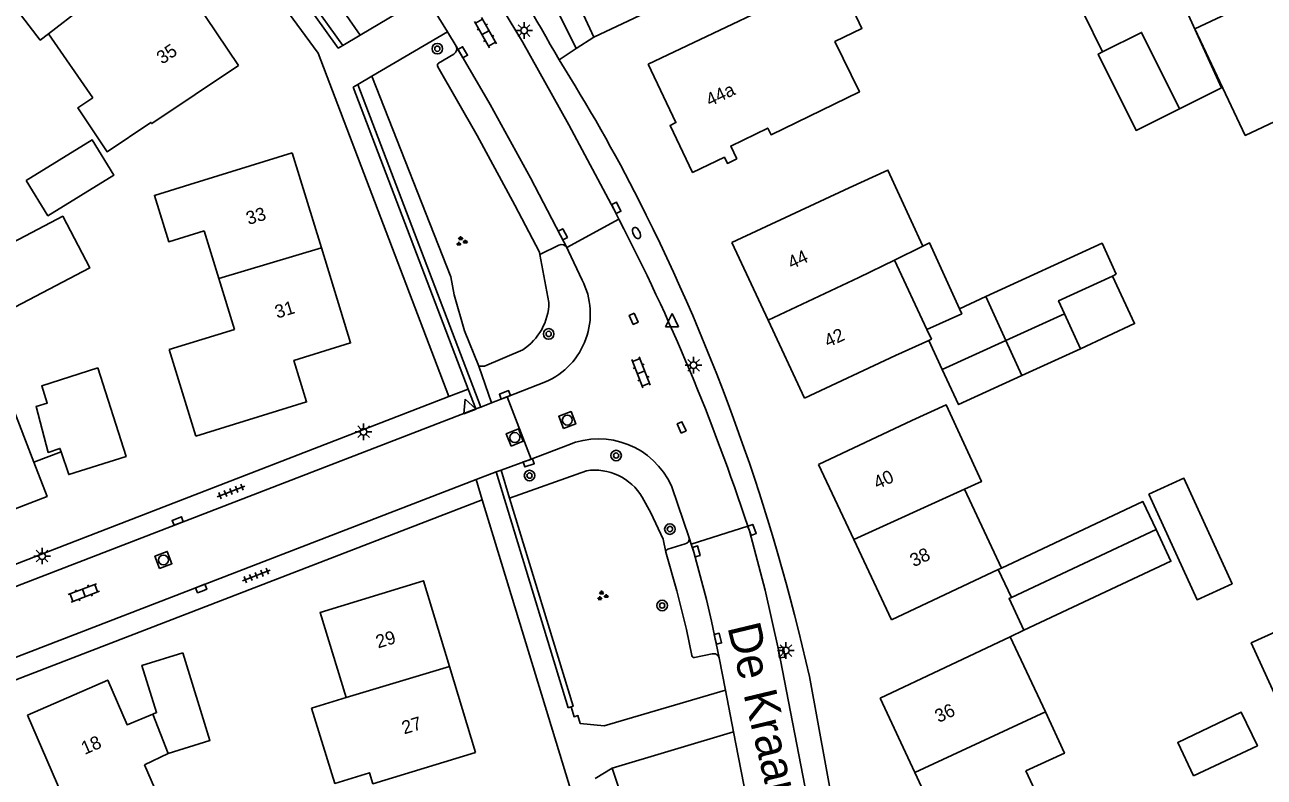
# Model space of a CAD drawing. Extents: x 136000 to 138005, y 398500 to 400500.
# Drawn here: x 137437.9 to 137531.8, y 399206.8 to 399263.7 of the extents above; entities that cross this region are included whole.
import ezdxf

# ---------------------------------------------------------------- set-up
doc = ezdxf.new("R2010")
doc.units = 0
for name, color, linetype in [('gg-afsc-erfafscheiding', 7, 'Continuous'), ('gg-anno-huisnummerreeks BGT', 7, 'Continuous'), ('gg-anno-openbare ruimte label', 7, 'Continuous'), ('gg-bbg-bijgebouw', 7, 'Continuous'), ('gg-bbg-gedigitaliseerde bebouwing', 7, 'Continuous'), ('gg-bbg-gedigitaliseerde bijgebouw', 7, 'Continuous'), ('gg-bbg-hoofdgebouw', 7, 'Continuous'), ('gg-bbg-luifel en loopbrug', 7, 'Continuous'), ('gg-bbg-tussenscheiding', 7, 'Continuous'), ('gg-knt-verharding', 7, 'Continuous'), ('gg-knt-verharding nz', 7, 'Continuous'), ('gt-grn-groengrens', 7, 'Continuous'), ('gt-grn-vlakafsluiter', 7, 'Continuous'), ('gt-grn-weggrens', 7, 'Continuous'), ('gt-symb-boom', 7, 'Continuous'), ('gt-symb-brandkraan', 7, 'Continuous'), ('gt-symb-groenvak', 7, 'Continuous'), ('gt-symb-klinker verharding', 7, 'Continuous'), ('gt-symb-kolk', 7, 'Continuous'), ('gt-symb-kolk center center', 7, 'Continuous'), ('gt-symb-lichtmast', 7, 'Continuous'), ('gt-symb-rioolschacht', 7, 'Continuous'), ('gt-symb-tegel verharding', 7, 'Continuous'), ('gt-symb-waterafsluiter', 7, 'Continuous')]:
    doc.layers.add(name, color=color, linetype=linetype)

# ---------------------------------------------------------------- blocks, each defined once
blk = doc.blocks.new('gt0-KOLK')
at = {"layer": 'gt-symb-kolk'}
blk.add_lwpolyline([(0, 0), (0.375, 0), (0.375, 0.4), (-0.375, 0.4), (-0.375, 0), (0, 0)], dxfattribs=at)
blk = doc.blocks.new('gt0-BOOM')
at = {"layer": 'gt-symb-boom'}
for radius in [0.4, 0.2]:
    blk.add_circle((0, 0), radius, dxfattribs=at)
blk = doc.blocks.new('gt0-KL1')
at = {"layer": 'gt-symb-klinker verharding'}
for p, q in [((-1.15, 0.3), (1.15, 0.3)), ((-1, -0.3), (-1, 0.3)), ((-0.5, 0.3), (-0.5, 0.45)), ((0, -0.3), (0, 0.3)), ((0.5, 0.3), (0.5, 0.45)), ((1, -0.3), (1, 0.3)), ((-1.15, -0.3), (1.15, -0.3)), ((-0.5, -0.45), (-0.5, -0.3)), ((0.5, -0.45), (0.5, -0.3))]:
    blk.add_line(p, q, dxfattribs=at)
blk = doc.blocks.new('gt0-LMAST')
at = {"layer": 'gt-symb-lichtmast'}
for p, q in [((-0.182, 0.173), (-0.447, 0.438)), ((-0.005, 0.246), (-0.005, 0.621)), ((0.172, 0.173), (0.437, 0.438)), ((-0.255, -0.004), (-0.63, -0.004)), ((-0.182, -0.181), (-0.447, -0.446)), ((-0.005, -0.254), (-0.005, -0.629)), ((0.437, -0.446), (0.172, -0.181)), ((0.245, -0.004), (0.62, -0.004))]:
    blk.add_line(p, q, dxfattribs=at)
blk.add_circle((-0.005, -0.004), 0.25, dxfattribs=at)
blk = doc.blocks.new('gt0-BR')
at = {"layer": 'gt-symb-brandkraan'}
for centre, radius, start, end in [((-0.244, 0), 0.206, 107.56694, 252.43307), ((0.599, -2.664), 3, 106.89205, 107.56694), ((0, -0.691), 0.938, 73.10799, 106.89205), ((-0.599, -2.664), 3, 72.43309, 73.10799), ((0.244, 0), 0.206, 287.56695, 72.43309), ((0.599, 2.664), 3, 252.43307, 253.10797), ((0, 0.691), 0.938, 253.10797, 286.89206), ((-0.599, 2.664), 3, 286.89206, 287.56695)]:
    blk.add_arc(centre, radius, start, end, dxfattribs=at)
blk = doc.blocks.new('gt0-GRVAK')
at = {"layer": 'gt-symb-groenvak'}
for p, q in [((-0.11, 0.189), (-0.228, 0.24)), ((-0.182, 0.153), (0.088, 0.153)), ((-0.091, 0.211), (-0.156, 0.322)), ((-0.047, 0.214), (-0.047, 0.393)), ((-0.004, 0.211), (0.061, 0.322)), ((0.015, 0.189), (0.133, 0.24)), ((0.262, -0.052), (0.197, 0.059)), ((0.305, -0.049), (0.305, 0.13)), ((0.349, -0.052), (0.414, 0.059)), ((-0.245, -0.228), (-0.363, -0.177)), ((-0.318, -0.264), (-0.047, -0.264)), ((-0.226, -0.206), (-0.291, -0.095)), ((-0.183, -0.203), (-0.183, -0.024)), ((-0.139, -0.206), (-0.074, -0.095)), ((-0.12, -0.228), (-0.002, -0.177)), ((0.243, -0.074), (0.125, -0.023)), ((0.17, -0.11), (0.441, -0.11)), ((0.368, -0.074), (0.486, -0.023))]:
    blk.add_line(p, q, dxfattribs=at)
blk = doc.blocks.new('gt0-KOLKCC')
at = {"layer": 'gt-symb-kolk center center'}
blk.add_lwpolyline([(-0.375, 0.2), (0.375, 0.2), (0.375, -0.2), (-0.375, -0.2)], close=True, dxfattribs=at)
blk = doc.blocks.new('gt0-RS')
at = {"layer": 'gt-symb-rioolschacht'}
blk.add_lwpolyline([(-0.5, -0.5), (0.5, -0.5), (0.5, 0.5), (-0.5, 0.5)], close=True, dxfattribs=at)
blk.add_circle((0, 0), 0.375, dxfattribs=at)
blk = doc.blocks.new('gt0-WAFSL')
at = {"layer": 'gt-symb-waterafsluiter'}
for p, q in [((-0.5, -0.333), (0, 0.667)), ((0, 0.667), (0.5, -0.333)), ((0.5, -0.333), (-0.5, -0.333))]:
    blk.add_line(p, q, dxfattribs=at)
blk = doc.blocks.new('gt0-TEG1')
at = {"layer": 'gt-symb-tegel verharding'}
for p, q in [((-1.125, 0), (1.125, 0)), ((-0.9, -0.25), (-0.9, 0.25)), ((-0.45, -0.25), (-0.45, 0.25)), ((0, -0.25), (0, 0.25)), ((0.45, -0.25), (0.45, 0.25)), ((0.9, -0.25), (0.9, 0.25))]:
    blk.add_line(p, q, dxfattribs=at)

msp = doc.modelspace()

# ---------------------------------------------------------------- linework, layer by layer
at = {"layer": 'gg-afsc-erfafscheiding'}
for p, q in [((137440.667, 399231.416), (137438.592, 399230.623)), ((137513.611, 399217.909), (137512.573, 399217.419))]:
    msp.add_line(p, q, dxfattribs=at)
at = {"layer": 'gg-bbg-bijgebouw'}
for p, q in [((137481.033, 399262.812), (137478.609, 399268.051)), ((137512.664, 399220.385), (137511.664, 399222.506))]:
    msp.add_line(p, q, dxfattribs=at)
for points in [[(137489.14, 399266.43), (137487.24, 399265.52), (137487.14, 399265.71), (137481.033, 399262.812)], [(137443.464, 399237.779), (137445.593, 399231.072), (137441.252, 399229.697), (137440.667, 399231.416)], [(137513.611, 399217.909), (137512.484, 399220.3), (137512.664, 399220.385)], [(137447.607, 399211.549), (137447.9, 399211.67), (137446.79, 399215.251), (137449.89, 399216.2)], [(137526.46, 399206.883), (137525.262, 399209.418), (137530.073, 399211.704), (137531.297, 399209.161), (137526.46, 399206.883)]]:
    msp.add_lwpolyline(points, dxfattribs=at)
at = {"layer": 'gg-bbg-gedigitaliseerde bebouwing'}
for p, q in [((137439.706, 399263.064), (137443.067, 399258.213)), ((137450.43, 399251.657), (137458.18, 399254.04)), ((137491.49, 399247.27), (137500.359, 399251.401)), ((137452.615, 399244.547), (137451.51, 399248.143)), ((137503.804, 399245.927), (137505.939, 399246.975)), ((137503.804, 399245.927), (137506.259, 399240.662)), ((137453.808, 399240.667), (137452.615, 399244.547)), ((137448.86, 399239.169), (137453.808, 399240.667)), ((137503.866, 399238.698), (137506.393, 399239.853)), ((137503.866, 399238.698), (137496.99, 399235.48)), ((137498.05, 399230.46), (137505.125, 399233.778)), ((137509.106, 399228.578), (137511.901, 399222.617)), ((137515.243, 399211.726), (137512.573, 399217.419)), ((137448.785, 399208.565), (137446.993, 399207.711))]:
    msp.add_line(p, q, dxfattribs=at)
for points in [[(137485.13, 399260.76), (137499.416, 399267.555), (137501.331, 399263.463), (137499.29, 399262.47), (137501.139, 399258.666), (137494.447, 399255.413), (137494.198, 399255.926), (137491.392, 399254.562), (137491.86, 399253.6)], [(137443.067, 399258.213), (137441.929, 399257.452), (137444.146, 399254.134), (137447.472, 399256.356), (137447.533, 399256.265), (137454.11, 399260.66)], [(137505.939, 399246.975), (137503.301, 399252.746), (137500.359, 399251.401)], [(137451.51, 399248.143), (137448.825, 399247.317), (137447.744, 399250.831), (137450.43, 399251.657)], [(137506.259, 399240.662), (137506.594, 399239.945), (137506.393, 399239.853)], [(137438.592, 399230.623), (137436.883, 399235.097), (137430.181, 399232.495)], [(137509.106, 399228.578), (137510.381, 399229.161), (137507.726, 399234.967), (137505.125, 399233.778)], [(137533.687, 399218.253), (137530.833, 399216.949), (137534.06, 399209.89)], [(137459.65, 399212.01), (137461.416, 399206.307), (137464.033, 399207.118), (137464.288, 399206.292), (137472.06, 399208.65)], [(137515.243, 399211.726), (137516.675, 399208.593), (137513.754, 399207.258)], [(137446.993, 399207.711), (137448.676, 399203.841), (137445.46, 399202.444), (137444.336, 399205.033), (137441.467, 399203.787), (137438.12, 399211.49)], [(137513.754, 399207.258), (137515.158, 399204.246), (137508.2, 399200.99)]]:
    msp.add_lwpolyline(points, dxfattribs=at)
at = {"layer": 'gg-bbg-gedigitaliseerde bijgebouw'}
for p, q in [((137525.397, 399257.383), (137528.583, 399258.972)), ((137520.317, 399244.72), (137520.607, 399244.853)), ((137510.712, 399243.173), (137512.231, 399239.849)), ((137512.231, 399239.849), (137513.449, 399237.184)), ((137513.449, 399237.184), (137517.901, 399239.219))]:
    msp.add_line(p, q, dxfattribs=at)
for points in [[(137439.706, 399263.064), (137439.088, 399262.587), (137434.814, 399268.131), (137437.982, 399270.573), (137439.826, 399268.182)], [(137528.583, 399258.972), (137524.551, 399267.823), (137518.118, 399264.62), (137519.571, 399261.697)], [(137526.555, 399263.445), (137534.638, 399267.258), (137538.451, 399259.175), (137530.368, 399255.362), (137526.555, 399263.445)], [(137519.571, 399261.697), (137522.523, 399263.164), (137525.397, 399257.383)], [(137438.026, 399251.963), (137439.669, 399249.289), (137444.666, 399252.359), (137443.022, 399255.033), (137438.026, 399251.963)], [(137434.107, 399245.759), (137436.157, 399241.838), (137442.84, 399245.332), (137440.791, 399249.253), (137434.107, 399245.759)], [(137520.607, 399244.853), (137519.532, 399247.204), (137510.712, 399243.173)], [(137520.317, 399244.72), (137521.993, 399241.128), (137517.901, 399239.219)], [(137440.667, 399231.416), (137440.581, 399231.669), (137439.697, 399231.368), (137438.772, 399234.837), (137439.614, 399235.098), (137439.207, 399236.409), (137443.464, 399237.779)], [(137523.078, 399228.207), (137525.721, 399229.415), (137529.372, 399221.429), (137526.722, 399220.218), (137523.078, 399228.207)], [(137511.901, 399222.617), (137522.624, 399227.646), (137523.619, 399225.523)], [(137523.619, 399225.523), (137524.742, 399223.129), (137513.611, 399217.909)], [(137449.89, 399216.2), (137451.94, 399209.549), (137448.785, 399208.565)]]:
    msp.add_lwpolyline(points, dxfattribs=at)
at = {"layer": 'gg-bbg-hoofdgebouw'}
for p, q in [((137458.18, 399254.04), (137460.39, 399246.85)), ((137494.24, 399241.375), (137491.49, 399247.27)), ((137496.99, 399235.48), (137494.24, 399241.375)), ((137450.88, 399232.59), (137448.86, 399239.169)), ((137498.05, 399230.46), (137500.71, 399224.789)), ((137500.71, 399224.789), (137503.57, 399218.69)), ((137503.57, 399218.69), (137511.664, 399222.506)), ((137512.573, 399217.419), (137502.71, 399212.77)), ((137472.06, 399208.65), (137470.09, 399215.155)), ((137462.27, 399212.81), (137459.65, 399212.01)), ((137505.332, 399207.144), (137502.71, 399212.77)), ((137508.2, 399200.99), (137505.332, 399207.144))]:
    msp.add_line(p, q, dxfattribs=at)
for points in [[(137446.25, 399268.46), (137448.12, 399265.66), (137449.95, 399266.88), (137454.11, 399260.66)], [(137491.86, 399253.6), (137491.14, 399253.25), (137490.92, 399253.71), (137488.5, 399252.56), (137486.8, 399256.13), (137487.24, 399256.34), (137485.13, 399260.76)], [(137460.39, 399246.85), (137462.6, 399239.66), (137458.3, 399238.33), (137459.27, 399235.19), (137450.88, 399232.59)], [(137428.588, 399227.104), (137431.315, 399228.187), (137432.435, 399225.275), (137439.613, 399228.037), (137438.592, 399230.623)], [(137470.09, 399215.155), (137468.12, 399221.66), (137460.29, 399219.241), (137462.27, 399212.81)], [(137438.12, 399211.49), (137444.2, 399214.13), (137445.67, 399210.751), (137447.607, 399211.549)]]:
    msp.add_lwpolyline(points, dxfattribs=at)
at = {"layer": 'gg-bbg-luifel en loopbrug'}
for p, q in [((137510.712, 399243.173), (137508.729, 399242.248)), ((137507.42, 399237.65), (137506.393, 399239.853)), ((137512.231, 399239.849), (137507.42, 399237.65))]:
    msp.add_line(p, q, dxfattribs=at)
for points in [[(137525.397, 399257.383), (137522.108, 399255.748), (137519.234, 399261.529), (137519.571, 399261.697)], [(137508.729, 399242.248), (137506.454, 399247.223), (137505.939, 399246.975)], [(137506.259, 399240.662), (137508.901, 399241.87), (137508.729, 399242.248)], [(137513.449, 399237.184), (137508.66, 399234.995), (137507.42, 399237.65)]]:
    msp.add_lwpolyline(points, dxfattribs=at)
at = {"layer": 'gg-bbg-tussenscheiding'}
for p, q in [((137439.706, 399263.064), (137442.256, 399265.029)), ((137452.615, 399244.547), (137460.39, 399246.85)), ((137501.111, 399244.605), (137503.804, 399245.927)), ((137494.24, 399241.375), (137501.111, 399244.605)), ((137512.231, 399239.849), (137516.691, 399241.865)), ((137517.901, 399239.219), (137516.691, 399241.865)), ((137500.71, 399224.789), (137509.106, 399228.578)), ((137512.664, 399220.385), (137523.619, 399225.523)), ((137511.664, 399222.506), (137511.901, 399222.617)), ((137462.27, 399212.81), (137470.09, 399215.155)), ((137505.332, 399207.144), (137515.243, 399211.726)), ((137447.607, 399211.549), (137448.785, 399208.565))]:
    msp.add_line(p, q, dxfattribs=at)
msp.add_lwpolyline([(137516.691, 399241.865), (137516.238, 399242.857), (137520.317, 399244.72)], dxfattribs=at)
at = {"layer": 'gg-knt-verharding'}
for p, q in [((137462.006, 399262.18), (137455.776, 399270.874)), ((137468.268, 399265.902), (137463.332, 399262.968)), ((137468.268, 399265.902), (137469.945, 399263.214)), ((137463.332, 399262.968), (137462.006, 399262.18)), ((137464.208, 399259.854), (137469.945, 399263.214)), ((137469.945, 399263.214), (137470.596, 399262.112)), ((137469.268, 399260.834), (137470.416, 399261.53)), ((137463.137, 399259.227), (137464.208, 399259.854)), ((137462.787, 399259.022), (137463.137, 399259.227)), ((137471.51, 399236.158), (137462.787, 399259.022)), ((137482.93, 399249.016), (137478.981, 399246.889)), ((137482.93, 399249.016), (137482.946, 399248.983)), ((137478.384, 399247.058), (137476.947, 399246.34)), ((137478.981, 399246.889), (137479.095, 399246.593)), ((137479.095, 399246.593), (137480.146, 399244.416)), ((137472.08, 399234.663), (137471.51, 399236.158)), ((137477.374, 399236.719), (137474.459, 399235.58)), ((137432.96, 399221.251), (137470.04, 399235.59)), ((137472.454, 399234.807), (137473.28, 399235.126)), ((137474.459, 399235.58), (137473.28, 399235.126)), ((137474.459, 399235.58), (137476.281, 399230.854)), ((137434.86, 399220.31), (137472.08, 399234.663)), ((137472.08, 399234.663), (137472.454, 399234.807)), ((137476.281, 399230.854), (137479.062, 399231.927)), ((137474.002, 399230.029), (137476.281, 399230.854)), ((137472.107, 399229.308), (137473.625, 399229.893)), ((137473.625, 399229.893), (137474.002, 399230.029)), ((137479.069, 399212.034), (137473.625, 399229.893)), ((137434.276, 399214.719), (137472.107, 399229.308)), ((137486.898, 399228.829), (137486.926, 399228.764)), ((137486.926, 399228.764), (137488.252, 399224.902)), ((137434.808, 399213.23), (137472.57, 399227.79)), ((137472.57, 399227.79), (137490.16, 399170.17)), ((137488.397, 399224.435), (137492.689, 399225.774)), ((137492.7, 399225.74), (137492.689, 399225.774)), ((137488.252, 399224.902), (137488.397, 399224.435)), ((137486.62, 399224.036), (137487.939, 399224.443)), ((137489.99, 399216.112), (137488.654, 399215.842)), ((137490.523, 399215.817), (137490.995, 399213.383)), ((137491.611, 399210.229), (137490.995, 399213.383)), ((137479.069, 399212.034), (137479.314, 399212.109)), ((137482.425, 399207.465), (137491.611, 399210.229)), ((137492.556, 399205.299), (137491.611, 399210.229)), ((137481.118, 399206.683), (137482.425, 399207.465))]:
    msp.add_line(p, q, dxfattribs=at)
for points in [[(137470.04, 399235.59), (137460.14, 399261.59), (137437.11, 399292.9)], [(137466.529, 399276.874), (137470.719, 399270.553), (137475.616, 399262.458), (137479.14, 399256.157), (137482.55, 399249.792), (137482.93, 399249.016)], [(137462.006, 399262.18), (137461.661, 399261.975), (137455.573, 399270.471)], [(137476.911, 399246.53), (137475.049, 399250.075), (137472.195, 399255.355), (137469.197, 399260.571)], [(137501.373, 399180.068), (137501.303, 399182.332), (137501.053, 399184.312), (137497.311, 399204.558), (137495.009, 399216.412), (137494, 399220.938), (137492.821, 399225.426), (137492.7, 399225.74)], [(137488.44, 399215.987), (137488.046, 399217.956), (137487.321, 399220.902), (137486.49, 399223.816)], [(137505.616, 399168.854), (137502.455, 399186.463), (137497.358, 399214.397)], [(137490.995, 399213.383), (137481.803, 399210.659), (137479.996, 399210.838)], [(137479.996, 399210.838), (137479.822, 399211.441), (137479.534, 399211.357), (137479.314, 399212.109)]]:
    msp.add_lwpolyline(points, dxfattribs=at)
for centre, radius, start, end in [((137277.273, 399146.937), 231.258, 29.57859, 34.91921), ((137470.211, 399261.912), 0.434, 298.21726, 27.41133), ((137469.391, 399260.66), 0.213, 125.23385, 204.55106), ((137364.346, 399189.206), 134.811, 27.00352, 32.22345), ((137345.757, 399180.429), 155.36, 12.62914, 26.77462), ((137344.876, 399177.373), 155.535, 18.13107, 27.41368), ((137478.589, 399246.643), 0.463, 32.07851, 116.30976), ((137475.154, 399241.866), 5.605, 293.32859, 27.05942), ((137481.388, 399226.351), 6.042, 24.21371, 112.64309), ((137487.859, 399224.833), 0.399, 281.52067, 9.89783), ((137486.696, 399223.843), 0.208, 111.49045, 187.35109), ((137488.637, 399216.047), 0.206, 196.98975, 274.76946), ((137490.115, 399215.709), 0.422, 14.79418, 107.27932)]:
    msp.add_arc(centre, radius, start, end, dxfattribs=at)
at = {"layer": 'gg-knt-verharding nz'}
for points in [[(137478.981, 399246.889), (137478.501, 399247.786), (137476.239, 399252.15), (137473.174, 399257.716), (137470.596, 399262.112)], [(137490.523, 399215.817), (137489.946, 399218.599), (137489.564, 399220.226), (137488.597, 399223.821), (137488.397, 399224.435)]]:
    msp.add_lwpolyline(points, dxfattribs=at)
at = {"layer": 'gt-grn-groengrens'}
for p, q in [((137456.661, 399272.525), (137463.332, 399262.968)), ((137472.454, 399234.807), (137463.137, 399259.227)), ((137476.911, 399246.53), (137476.947, 399246.34)), ((137476.947, 399246.34), (137477.627, 399242.719)), ((137475.637, 399239.143), (137472.742, 399237.902)), ((137472.313, 399237.9), (137472.742, 399237.902)), ((137472.313, 399237.9), (137473.28, 399235.126)), ((137474.647, 399227.911), (137474.002, 399230.029)), ((137480.465, 399229.979), (137474.647, 399227.911)), ((137486.49, 399223.816), (137486.281, 399224.804)), ((137487.233, 399192.644), (137482.425, 399207.465))]:
    msp.add_line(p, q, dxfattribs=at)
for points in [[(137471.024, 399283.344), (137469.488, 399282.565), (137479.696, 399261.94)], [(137464.208, 399259.854), (137470.199, 399244.656), (137470.433, 399243.287), (137471.239, 399240.579), (137472.313, 399237.9)], [(137479.314, 399212.109), (137479.452, 399212.151), (137474.647, 399227.911)], [(137486.281, 399224.804), (137485.334, 399226.8), (137484.692, 399227.983)]]:
    msp.add_lwpolyline(points, dxfattribs=at)
for centre, radius, start, end in [((137473.27, 399242.802), 4.358, 302.8974, 358.9118), ((137481.093, 399225.836), 4.19, 30.82046, 98.62595)]:
    msp.add_arc(centre, radius, start, end, dxfattribs=at)
at = {"layer": 'gt-grn-vlakafsluiter'}
for p, q in [((137481.033, 399262.812), (137479.696, 399261.94)), ((137479.696, 399261.94), (137478.393, 399261.09))]:
    msp.add_line(p, q, dxfattribs=at)
at = {"layer": 'gt-grn-weggrens'}
for p, q in [((137470.04, 399235.59), (137471.51, 399236.158)), ((137472.107, 399229.308), (137472.57, 399227.79))]:
    msp.add_line(p, q, dxfattribs=at)

# ---------------------------------------------------------------- block references
at = {"layer": 'gt-symb-boom'}
for p in [(137469.169, 399261.931), (137477.604, 399240.338), (137482.714, 399231.132), (137476.156, 399229.617), (137486.79, 399225.566), (137486.201, 399219.783)]:
    msp.add_blockref('gt0-BOOM', p, dxfattribs=at)
at = {"layer": 'gt-symb-brandkraan', "rotation": -63.89617500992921}
msp.add_blockref('gt0-BR', (137484.258, 399247.978), dxfattribs=at)
at = {"layer": 'gt-symb-groenvak'}
for p in [(137470.983, 399247.341), (137481.662, 399220.511)]:
    msp.add_blockref('gt0-GRVAK', p, dxfattribs=at)
at = {"layer": 'gt-symb-klinker verharding'}
for p, rotation in [((137472.816, 399263.144), -60.58918037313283), ((137484.608, 399237.428), -68.77323173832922), ((137442.391, 399220.736), 21.09921224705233)]:
    msp.add_blockref('gt0-KL1', p, dxfattribs=dict(at, rotation=rotation))
at = {"layer": 'gt-symb-kolk'}
for p, rotation in [((137470.923, 399261.553), -59.61055211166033), ((137482.55, 399249.792), -63.94764904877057), ((137478.501, 399247.786), -61.82166392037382), ((137474.362, 399235.543), 21.40773994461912), ((137476.025, 399230.766), -161.03974891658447), ((137449.573, 399225.986), 21.09921224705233), ((137492.821, 399225.426), -68.84735479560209), ((137488.597, 399223.821), -74.95578679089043), ((137451.356, 399220.878), 21.09921225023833), ((137490.229, 399217.224), -76.47852780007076), ((137495.037, 399216.199), -82.590815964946)]:
    msp.add_blockref('gt0-KOLK', p, dxfattribs=dict(at, rotation=rotation))
at = {"layer": 'gt-symb-kolk center center'}
for p, rotation in [((137484.041, 399241.483), -66.22952419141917), ((137487.676, 399233.263), 114.3348742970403)]:
    msp.add_blockref('gt0-KOLKCC', p, dxfattribs=dict(at, rotation=rotation))
at = {"layer": 'gt-symb-lichtmast'}
for p in [(137475.752, 399263.312), (137488.583, 399237.977), (137463.582, 399232.936), (137439.234, 399223.527), (137495.58, 399216.374)]:
    msp.add_blockref('gt0-LMAST', p, dxfattribs=at)
at = {"layer": 'gt-symb-rioolschacht'}
for p, rotation in [((137479.014, 399233.815), 21.09921225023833), ((137475.038, 399232.497), 21.09921224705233), ((137448.422, 399223.228), 21.09921225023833)]:
    msp.add_blockref('gt0-RS', p, dxfattribs=dict(at, rotation=rotation))
at = {"layer": 'gt-symb-tegel verharding'}
for p, rotation in [((137453.543, 399228.415), 21.09921224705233), ((137455.461, 399222.056), 21.09921225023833)]:
    msp.add_blockref('gt0-TEG1', p, dxfattribs=dict(at, rotation=rotation))
at = {"layer": 'gt-symb-waterafsluiter'}
msp.add_blockref('gt0-WAFSL', (137486.947, 399241.22), dxfattribs=at)
at = {"layer": 'gt-symb-waterafsluiter', "rotation": 20.55604522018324}
msp.add_blockref('gt0-WAFSL', (137471.523, 399234.775), dxfattribs=at)

# ---------------------------------------------------------------- texts
at = {"layer": 'gg-anno-huisnummerreeks BGT'}
for s, rotation, p in [('35', 33.8, (137448.326, 399260.714)), ('44a', 25.5, (137489.812, 399257.532)), ('33', 17.1, (137454.86, 399248.581)), ('44', 25, (137496.006, 399245.216)), ('31', 17.1, (137457.038, 399241.494)), ('42', 25, (137498.77, 399239.291)), ('40', 25.2, (137502.504, 399228.556)), ('38', 25.2, (137505.264, 399222.671)), ('29', 16.9, (137464.684, 399216.526)), ('36', 25, (137507.146, 399210.881)), ('27', 16.9, (137466.655, 399210.017)), ('18', 23.5, (137442.456, 399208.466))]:
    msp.add_text(s, height=1, rotation=rotation, dxfattribs=at).set_placement(p)
at = {"layer": 'gg-anno-openbare ruimte label'}
msp.add_text('De Kraan', height=2.5, rotation=283.5, dxfattribs=at).set_placement((137491.134, 399218.151))

doc.saveas('drawing.dxf')
